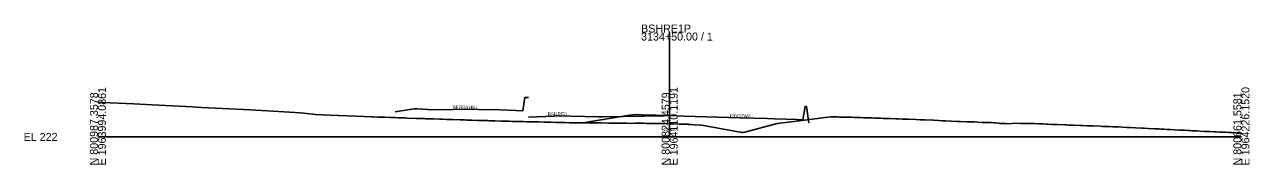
# Model space of a CAD drawing. Extents: x -26 to 403, y -10 to 6039.
# Drawn here: x -25.7 to 402.8, y 5990.3 to 6039.4 of the extents above; entities that cross this region are included whole.
import ezdxf

# ---------------------------------------------------------------- set-up
doc = ezdxf.new("R2010")
doc.units = 0
for name, color, linetype in [('Default', 7, 'Continuous'), ('RD_GPK_XS_Cell', 7, 'Continuous'), ('RD_TX_Misc1', 7, 'Continuous'), ('RD_XS_ExGround', 7, 'Continuous'), ('RD_XS_Pave', 7, 'Continuous'), ('RD_XS_TX_Elev_EX', 7, 'Continuous')]:
    doc.layers.add(name, color=color, linetype=linetype)

msp = doc.modelspace()

# ---------------------------------------------------------------- linework, layer by layer
at = {"layer": 'RD_GPK_XS_Cell'}
for p, q in [((200, 6000), (200, 6036.57)), ((0, 6000), (200, 6000)), ((200, 6000), (400, 6000))]:
    msp.add_line(p, q, dxfattribs=at)
at = {"layer": 'RD_XS_ExGround'}
msp.add_lwpolyline([(0, 6012.19), (1.68, 6012.11), (12.57, 6011.55), (18.94, 6011.24), (32.91, 6010.51), (36.23, 6010.35), (53.39, 6009.45), (55.19, 6009.35), (61.34, 6008.98), (70.72, 6008.48), (75.25, 6007.92), (76.1, 6007.82), (78.43, 6007.74), (83.89, 6007.51), (84.21, 6007.5), (95.88, 6007.04), (96.38, 6007.02), (97.91, 6006.96), (99.14, 6006.91), (100.4, 6006.87), (102.07, 6006.81), (102.43, 6006.79), (103.98, 6006.76), (105.16, 6006.7), (105.82, 6006.68), (106.75, 6006.64), (107.6, 6006.67), (108.22, 6006.6), (111.3, 6006.49), (112.99, 6006.44), (114.36, 6006.39), (114.76, 6006.38), (115.33, 6006.36), (116.58, 6006.32), (117.44, 6006.29), (119.63, 6006.22), (120.14, 6006.21), (120.51, 6006.19), (121.95, 6006.14), (123.58, 6006.1), (124, 6006.08), (126.66, 6005.99), (127.33, 6005.97), (128.27, 6005.94), (129.12, 6005.92), (129.72, 6005.9), (130.91, 6005.86), (132.79, 6005.8), (134.49, 6005.74), (135.86, 6005.7), (136.29, 6005.69), (136.9, 6005.67), (138.92, 6005.62), (141.22, 6005.56), (141.68, 6005.55), (142, 6005.54), (143.85, 6005.48), (145.05, 6005.45), (145.55, 6005.43), (148.14, 6005.37), (148.84, 6005.35), (149.82, 6005.33), (151.21, 6005.3), (152.41, 6005.27), (154.27, 6005.22), (156.01, 6005.18), (157.35, 6005.14), (157.8, 6005.13), (158.45, 6005.12), (160.42, 6005.08), (161.38, 6005.05), (162.75, 6005.01), (163.18, 6005), (163.49, 6004.99), (164.96, 6004.96), (167.05, 6004.93), (168.55, 6004.93), (169.63, 6004.9), (170.36, 6004.9), (171.38, 6004.91), (172.68, 6004.92), (175.94, 6004.89), (178.67, 6004.84), (179.3, 6004.82), (180.02, 6004.81), (181.86, 6004.79), (184.36, 6004.76), (184.93, 6004.76), (186.4, 6004.75), (188, 6004.78), (188.67, 6004.77), (190.08, 6004.77), (191.08, 6004.76), (191.87, 6004.75), (192.99, 6004.75), (193.66, 6004.74), (194.15, 6004.74), (195.45, 6004.73), (197.41, 6004.69), (200.3, 6004.61), (201.5, 6004.57), (203.34, 6004.51), (205.91, 6004.42), (206.33, 6004.41), (206.71, 6004.38), (207.55, 6004.33), (208.61, 6004.27), (211.23, 6004.07), (225.2, 6001.55), (225.5, 6001.49), (226.24, 6001.69), (237.61, 6004.67), (245.25, 6005.68), (256.26, 6007.02), (257.54, 6007.01), (258.82, 6006.98), (259.29, 6006.97), (259.98, 6006.96), (261.8, 6006.92), (263.6, 6006.86), (264.78, 6006.82), (265.36, 6006.8), (266.81, 6006.75), (267.79, 6006.72), (268.94, 6006.68), (270.92, 6006.63), (271.76, 6006.6), (274, 6006.52), (274.71, 6006.49), (276.15, 6006.44), (277.08, 6006.41), (279.08, 6006.35), (280.06, 6006.32), (281.47, 6006.27), (283.57, 6006.19), (286.25, 6006.07), (287.67, 6006), (288.66, 6005.96), (289.31, 6005.93), (292.01, 6005.82), (292.36, 6005.81), (294.06, 6005.74), (295.47, 6005.68), (296.44, 6005.63), (298.52, 6005.54), (300.62, 6005.44), (301.22, 6005.41), (301.6, 6005.4), (303.91, 6005.32), (304.88, 6005.28), (306.58, 6005.22), (307.77, 6005.17), (309.26, 6005.1), (310.73, 6005.04), (311.79, 6005.01), (312.47, 6004.99), (313.48, 6004.92), (313.89, 6004.89), (314.77, 6004.77), (315.08, 6004.76), (315.53, 6004.74), (316.92, 6004.66), (317.59, 6004.64), (318.28, 6004.62), (319.79, 6004.71), (321.15, 6004.8), (322.53, 6004.71), (323.15, 6004.68), (324.34, 6004.64), (324.74, 6004.71), (325.1, 6004.69), (326.4, 6004.69), (326.97, 6004.68), (327.49, 6004.66), (329.21, 6004.58), (330.72, 6004.52), (331.66, 6004.48), (332.31, 6004.46), (333.53, 6004.4), (335.37, 6004.32), (335.83, 6004.3), (338.39, 6004.19), (338.83, 6004.17), (339.5, 6004.15), (341.43, 6004.09), (343.59, 6004.02), (344.13, 6004), (344.52, 6003.98), (346.01, 6003.93), (348.15, 6003.85), (350.71, 6003.73), (351.41, 6003.7), (352.44, 6003.67), (353.24, 6003.64), (353.79, 6003.61), (355.06, 6003.56), (356.89, 6003.48), (359.93, 6003.33), (361.06, 6003.27), (362.98, 6003.17), (365.16, 6003.07), (366.02, 6003.03), (367.45, 6002.96), (369.49, 6002.86), (371.07, 6002.78), (372.16, 6002.72), (372.88, 6002.68), (373.91, 6002.62), (374.69, 6002.57), (375.23, 6002.55), (376.49, 6002.49), (378.31, 6002.4), (380.1, 6002.3), (381.39, 6002.24), (381.93, 6002.22), (382.67, 6002.18), (384.45, 6002.08), (385.51, 6002.02), (386.98, 6001.94), (387.49, 6001.92), (388.8, 6001.86), (390.59, 6001.78), (391.3, 6001.75), (392.47, 6001.69), (393.69, 6001.63), (394.44, 6001.6), (395.47, 6001.55), (396.21, 6001.52), (396.69, 6001.49), (398.04, 6001.42), (398.5, 6001.36), (399.13, 6001.32), (399.51, 6001.29), (399.94, 6001.26), (400, 6001.25)], dxfattribs=at)
at = {"layer": 'RD_XS_Pave'}
for points in [[(103.94, 6008.74), (108.3, 6009.47), (110.63, 6009.86), (111.72, 6009.82), (113.63, 6009.76), (115.54, 6009.57), (116.63, 6009.46), (124.23, 6009.61), (128.63, 6009.7), (133.1, 6009.62), (140.64, 6009.47), (143.65, 6009.35), (148.64, 6009.15), (149.39, 6013.82), (149.86, 6013.82), (150.64, 6013.82)], [(169.71, 6004.91), (173.13, 6005.48), (186, 6007.64), (186.37, 6007.67), (188, 6007.8), (190.25, 6007.73), (200, 6007.44), (200, 6007.44), (200, 6007.44), (204.98, 6007.3), (224.64, 6006.72), (234.18, 6006.44), (236.64, 6006.36), (244.55, 6006.05), (246.64, 6005.97), (247.39, 6010.64), (247.89, 6010.64), (248.64, 6004.97)], [(150.59, 6006.96), (159.57, 6007.32), (160.59, 6007.36), (175.11, 6007.08), (176.59, 6007.05), (198.1, 6007.41), (200, 6007.44)]]:
    msp.add_lwpolyline(points, dxfattribs=at)

# ---------------------------------------------------------------- texts
at = {"layer": 'Default'}
msp.add_text('-', height=0.0001, dxfattribs=at).set_placement((0, 6000))
at = {"layer": 'RD_GPK_XS_Cell'}
for s, p in [('BSHRE1P', (190, 6036.57)), ('3134+50.00 / 1', (190, 6033.77)), ('EL 222', (-26, 5998.6))]:
    msp.add_text(s, height=2.8, dxfattribs=at).set_placement(p)
for s, p in [('E 1963994.0861', (2.8, 5990)), ('E 1964110.1191', (202.8, 5990)), ('E 1964226.1520', (402.8, 5990)), ('N 800987.3578', (0, 5990)), ('N 800824.4579', (200, 5990)), ('N 800661.5581', (400, 5990))]:
    msp.add_text(s, height=2.8, rotation=90, dxfattribs=at).set_placement(p)
at = {"layer": 'RD_TX_Misc1'}
for s, p in [('BERRYHILL', (124.06, 6009.76)), ('BSHRE0', (157.34, 6007.36)), ('I20CDW2', (221.1, 6006.72))]:
    msp.add_text(s, height=1.2, dxfattribs=at).set_placement(p)
at = {"layer": 'RD_XS_TX_Elev_EX'}
msp.add_text('226.62', height=1, dxfattribs=at).set_placement((197.9, 6002.12))

doc.saveas('drawing.dxf')
